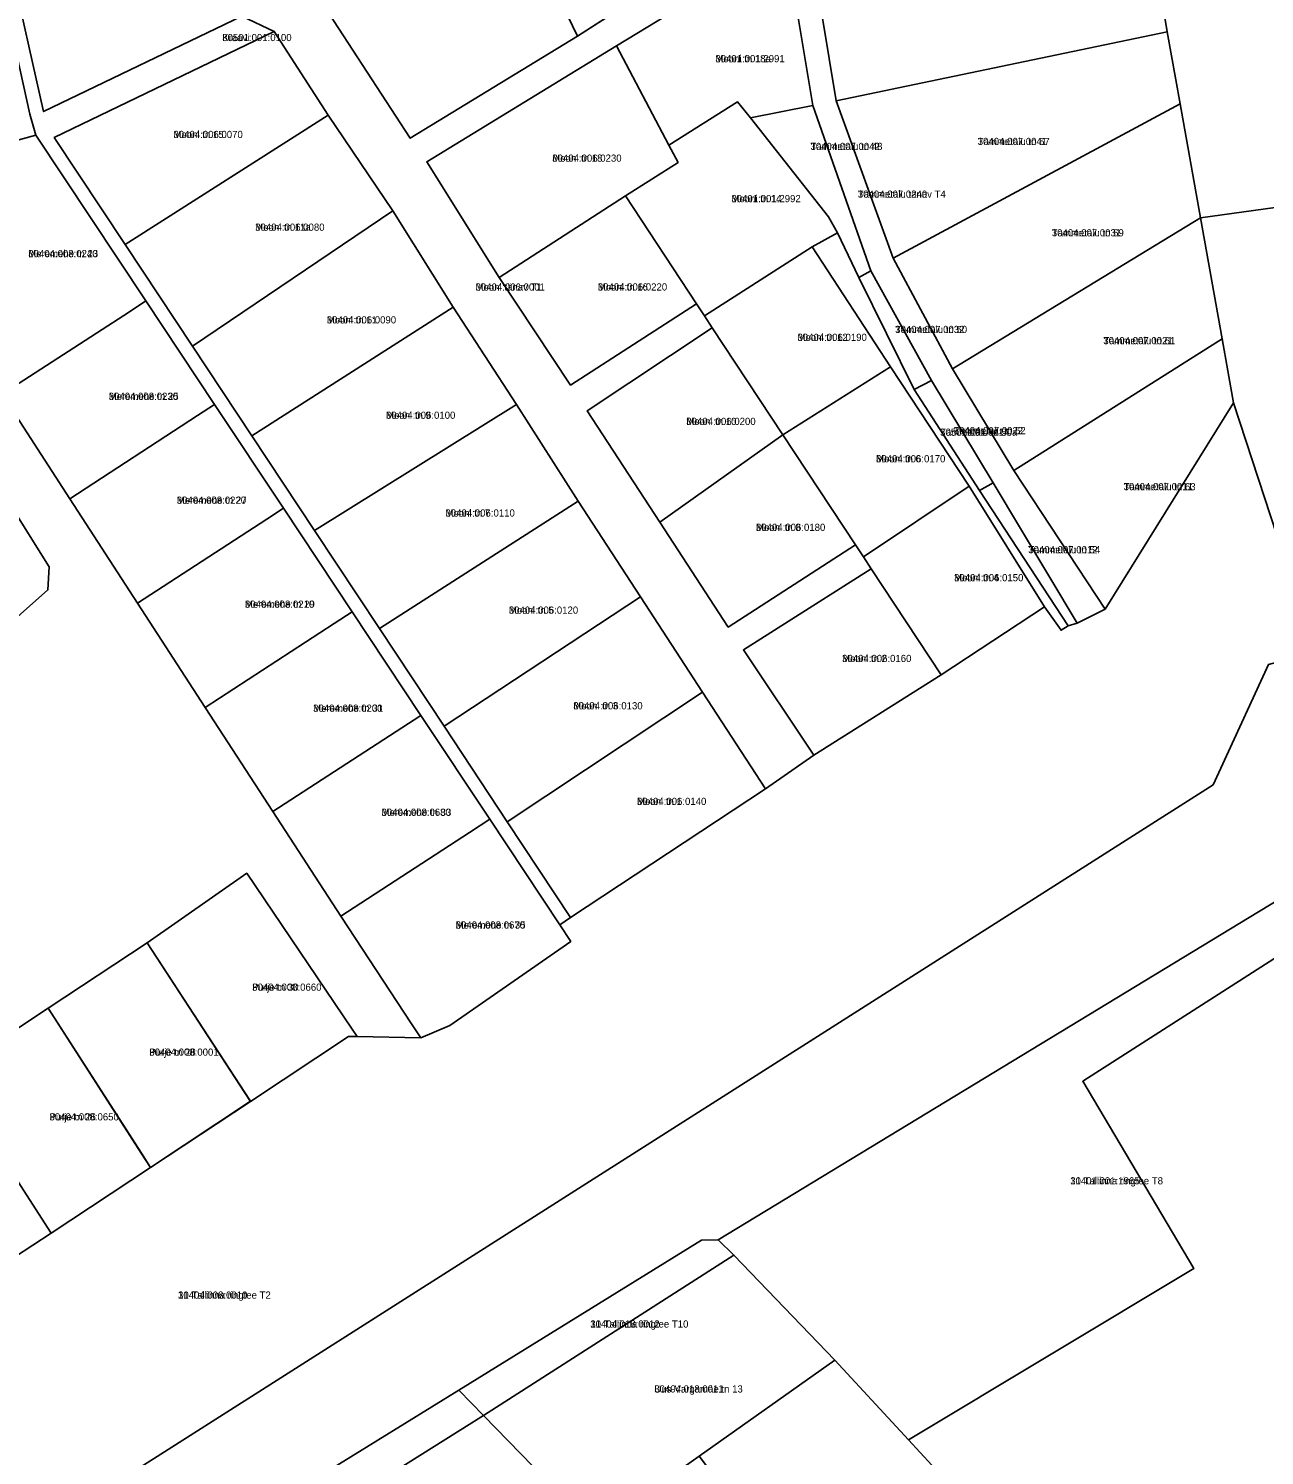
# Model space of a CAD drawing. Extents: x 542681 to 554572, y 6566489 to 6580482.
# Drawn here: x 544263.2 to 544521.7, y 6576713.2 to 6577011.6 of the extents above; entities that cross this region are included whole.
import ezdxf

# ---------------------------------------------------------------- set-up
doc = ezdxf.new("R2010")
doc.units = 0
for name, color, linetype in [('L_AADRESS', 7, 'Continuous'), ('PIIR', 7, 'Continuous'), ('TUNNUS', 7, 'Continuous')]:
    doc.layers.add(name, color=color, linetype=linetype)

msp = doc.modelspace()

# ---------------------------------------------------------------- linework, layer by layer
at = {"layer": 'PIIR'}
for points in [[(544047.37, 6576558.6), (544511.03, 6576853.43), (544522.56, 6576878.58), (544532.39, 6576881.26), (544735.78, 6577003.33), (545244.51, 6577326.53)], [(544232.86, 6577132.75), (544263.5, 6576993.69), (544264.77, 6576989.29), (544238.54, 6576982.1)], [(544259.33, 6577025.66), (544266.36, 6576994.23), (544307.82, 6577014.16), (544314.6, 6577010.96), (544268.59, 6576988.8), (544283.42, 6576966.41), (544297.5, 6576945.15), (544309.92, 6576926.39), (544323.02, 6576906.59), (544336.6, 6576886.08), (544350.13, 6576865.65), (544363.36, 6576845.67), (544376.61, 6576825.66), (544374.32, 6576824.14), (544359.67, 6576846.22), (544345.3, 6576867.89), (544330.91, 6576889.58), (544316.53, 6576911.27), (544302.13, 6576932.97), (544287.78, 6576954.61), (544264.77, 6576989.29), (544263.5, 6576993.69), (544232.86, 6577132.75)], [(544980.83, 6577118.49), (544817.23, 6577014.55), (544631.37, 6576896.55), (544550.43, 6576845.06), (544407.49, 6576758.27), (544403.98, 6576758.21), (544353.21, 6576726.8), (544302.38, 6576695.41)], [(544427.82, 6577022.67), (544432.12, 6576996.45), (544444.03, 6576963.57), (544456.44, 6576940.4), (544469.29, 6576919.14), (544488.38, 6576890.18), (544482.53, 6576887.2), (544465.01, 6576916.58), (544452.06, 6576937.98), (544439.36, 6576960.91), (544427.25, 6576995.48), (544422.87, 6577021.89)], [(544325.07, 6577016.28), (544343.06, 6576988.63), (544378.03, 6577009.97), (544392.94, 6577019.63)], [(544396.97, 6577014.51), (544386.23, 6577007.95), (544346.5, 6576983.72), (544361.68, 6576959.52), (544376.6, 6576937.03), (544402.93, 6576954), (544404.58, 6576951.49), (544406.24, 6576948.99), (544380.04, 6576931.62), (544395.27, 6576908.38), (544409.56, 6576886.41), (544436.19, 6576903.58), (544437.84, 6576901.08), (544439.49, 6576898.58), (544412.73, 6576881.63), (544427.47, 6576859.62), (544417.35, 6576852.57), (544404.2, 6576872.77), (544391.22, 6576892.72), (544378.18, 6576912.76), (544365.28, 6576932.97), (544352.02, 6576953.35), (544339.42, 6576973.43), (544325.88, 6576993.45), (544314.6, 6577010.96), (544307.82, 6577014.16)], [(544257.68, 6576935.15), (544271.85, 6576913.23), (544285.99, 6576891.43), (544300.14, 6576869.62), (544314.29, 6576847.82), (544328.56, 6576825.97), (544343.3, 6576803.42), (544345.26, 6576800.49), (544331.93, 6576800.8), (544330.92, 6576802.29), (544308.86, 6576834.92), (544288.05, 6576820.34), (544267.31, 6576806.67), (544248.12, 6576794.02)], [(544183.03, 6576703.47), (544209.73, 6576721.14), (544236.26, 6576738.69), (544241.04, 6576742.08), (544267.97, 6576759.66), (544288.75, 6576773.4), (544309.62, 6576787.21), (544330.16, 6576800.8), (544331.93, 6576800.8), (544345.26, 6576800.49), (544351.31, 6576803.07), (544376.64, 6576820.65), (544374.32, 6576824.14), (544376.61, 6576825.66), (544417.35, 6576852.57), (544427.47, 6576859.62), (544454.09, 6576876.45), (544475.75, 6576890.64), (544479.2, 6576885.76), (544480.66, 6576886.66), (544482.53, 6576887.2), (544488.38, 6576890.18), (544515.24, 6576933.3), (544528.21, 6576893.68)], [(544255.76, 6576884.03), (544267.28, 6576894.17), (544267.52, 6576899.03), (544248.56, 6576929.2)], [(544522.56, 6576878.58), (544511.03, 6576853.43), (544047.37, 6576558.6)], [(544461.91, 6576700.54), (544447.29, 6576716.4), (544506.96, 6576752.28), (544483.71, 6576791.42), (544554.71, 6576836.87), (544590.03, 6576770.52), (544597.56, 6576756.49), (544648.05, 6576660.25)]]:
    msp.add_lwpolyline(points, dxfattribs=at)
for points in [[(544508.33, 6576971.98), (544504.11, 6576995.85), (544501.39, 6577010.89), (544497.94, 6577031.69), (544494.23, 6577050.54), (544821.86, 6577171.21), (545190.34, 6577306.46), (545193.01, 6577298.86), (545134.4, 6577265.31), (545034.06, 6577204.02), (544998.25, 6577194.68), (544965.83, 6577161.37), (544819.08, 6577074.48), (544704.29, 6576998.99), (544688.78, 6576996.97)], [(544346.42, 6577070.5), (544372.29, 6577074.64), (544377.9, 6577042.29), (544392.89, 6577019.62), (544378.03, 6577009.97), (544365.54, 6577035.85), (544363.91, 6577040.25), (544348.97, 6577033.42), (544343.71, 6577060.87), (544341.95, 6577069.79)], [(544259.33, 6577025.66), (544303.68, 6577034.31), (544307.82, 6577014.16), (544266.36, 6576994.23)], [(544343.06, 6576988.63), (544325.07, 6577016.28), (544365.54, 6577035.85), (544378.03, 6577009.97)], [(544501.39, 6577010.89), (544432.12, 6576996.45), (544427.82, 6577022.67), (544497.94, 6577031.69)], [(544411.54, 6576996.24), (544397.14, 6576987.19), (544386.23, 6577007.95), (544396.97, 6577014.51), (544394.09, 6577018.12), (544422.87, 6577021.89), (544427.25, 6576995.48), (544414.19, 6576992.91)], [(544268.59, 6576988.8), (544314.6, 6577010.96), (544325.88, 6576993.45), (544283.42, 6576966.41)], [(544504.11, 6576995.85), (544444.03, 6576963.57), (544432.12, 6576996.45), (544501.39, 6577010.89)], [(544361.68, 6576959.52), (544346.5, 6576983.72), (544386.23, 6577007.95), (544397.14, 6576987.19), (544399.07, 6576983.59), (544388.08, 6576976.57)], [(544427.1, 6576965.92), (544404.58, 6576951.49), (544402.93, 6576954), (544388.08, 6576976.57), (544399.07, 6576983.59), (544397.14, 6576987.19), (544411.54, 6576996.24), (544414.19, 6576992.91), (544430.54, 6576972.24), (544432.39, 6576968.87)], [(544439.36, 6576960.91), (544436.91, 6576959.51), (544432.39, 6576968.87), (544430.54, 6576972.24), (544414.19, 6576992.91), (544427.25, 6576995.48)], [(544508.33, 6576971.98), (544456.44, 6576940.4), (544444.03, 6576963.57), (544504.11, 6576995.85)], [(544515.24, 6576933.3), (544512.86, 6576946.66), (544508.33, 6576971.98), (544688.78, 6576996.97), (544528.21, 6576893.68)], [(544283.42, 6576966.41), (544325.88, 6576993.45), (544339.42, 6576973.43), (544297.5, 6576945.15)], [(544252.75, 6576942.7), (544239.47, 6576979.52), (544238.54, 6576982.1), (544264.77, 6576989.29), (544287.78, 6576954.61), (544284.32, 6576952.37), (544257.68, 6576935.15)], [(544361.68, 6576959.52), (544388.08, 6576976.57), (544402.93, 6576954), (544376.6, 6576937.03)], [(544297.5, 6576945.15), (544339.42, 6576973.43), (544352.02, 6576953.35), (544309.92, 6576926.39)], [(544512.86, 6576946.66), (544469.29, 6576919.14), (544456.44, 6576940.4), (544508.33, 6576971.98)], [(544480.66, 6576886.66), (544479.2, 6576885.76), (544475.75, 6576890.64), (544459.97, 6576915.88), (544443.54, 6576940.83), (544427.1, 6576965.92), (544432.39, 6576968.87), (544436.91, 6576959.51), (544448.48, 6576936.07), (544462.12, 6576914.94)], [(544404.58, 6576951.49), (544427.1, 6576965.92), (544443.54, 6576940.83), (544420.99, 6576926.62), (544406.24, 6576948.99)], [(544452.06, 6576937.98), (544448.48, 6576936.07), (544436.91, 6576959.51), (544439.36, 6576960.91)], [(544257.68, 6576935.15), (544284.32, 6576952.37), (544287.78, 6576954.61), (544302.13, 6576932.97), (544298.54, 6576930.63), (544271.85, 6576913.23)], [(544309.92, 6576926.39), (544352.02, 6576953.35), (544365.28, 6576932.97), (544323.02, 6576906.59)], [(544380.04, 6576931.62), (544406.24, 6576948.99), (544420.99, 6576926.62), (544395.27, 6576908.38)], [(544515.24, 6576933.3), (544488.38, 6576890.18), (544469.29, 6576919.14), (544512.86, 6576946.66)], [(544420.99, 6576926.62), (544443.54, 6576940.83), (544459.97, 6576915.88), (544437.84, 6576901.08), (544436.19, 6576903.58)], [(544465.01, 6576916.58), (544462.12, 6576914.94), (544448.48, 6576936.07), (544452.06, 6576937.98)], [(544271.85, 6576913.23), (544298.54, 6576930.63), (544302.13, 6576932.97), (544316.53, 6576911.27), (544313.03, 6576909), (544285.99, 6576891.43)], [(544323.02, 6576906.59), (544365.28, 6576932.97), (544378.18, 6576912.76), (544336.6, 6576886.08)], [(544236.42, 6576892.73), (544234.62, 6576892.27), (544226.19, 6576923.47), (544248.56, 6576929.2), (544267.52, 6576899.03), (544267.28, 6576894.17), (544255.76, 6576884.03), (544251.02, 6576892.37), (544240.1, 6576887.96)], [(544395.27, 6576908.38), (544420.99, 6576926.62), (544436.19, 6576903.58), (544409.56, 6576886.41)], [(544437.84, 6576901.08), (544459.97, 6576915.88), (544475.75, 6576890.64), (544454.09, 6576876.45), (544439.49, 6576898.58)], [(544482.53, 6576887.2), (544480.66, 6576886.66), (544462.12, 6576914.94), (544465.01, 6576916.58)], [(544285.99, 6576891.43), (544313.03, 6576909), (544316.53, 6576911.27), (544330.91, 6576889.58), (544327.16, 6576887.15), (544300.14, 6576869.62)], [(544336.6, 6576886.08), (544378.18, 6576912.76), (544391.22, 6576892.72), (544350.13, 6576865.65)], [(544412.73, 6576881.63), (544439.49, 6576898.58), (544454.09, 6576876.45), (544427.47, 6576859.62)], [(544350.13, 6576865.65), (544391.22, 6576892.72), (544404.2, 6576872.77), (544363.36, 6576845.67)], [(544300.14, 6576869.62), (544327.16, 6576887.15), (544330.91, 6576889.58), (544345.3, 6576867.89), (544341.3, 6576865.31), (544314.29, 6576847.82)], [(544363.36, 6576845.67), (544404.2, 6576872.77), (544417.35, 6576852.57), (544376.61, 6576825.66)], [(544314.29, 6576847.82), (544341.3, 6576865.31), (544345.3, 6576867.89), (544359.67, 6576846.22), (544355.44, 6576843.47), (544328.56, 6576825.97)], [(544345.26, 6576800.49), (544343.3, 6576803.42), (544328.56, 6576825.97), (544355.44, 6576843.47), (544359.67, 6576846.22), (544374.32, 6576824.14), (544376.64, 6576820.65), (544351.31, 6576803.07)], [(544407.49, 6576758.27), (544550.43, 6576845.06), (544552.67, 6576840.76), (544554.71, 6576836.87), (544483.71, 6576791.42), (544506.96, 6576752.28), (544447.29, 6576716.4), (544431.89, 6576733.07), (544410.75, 6576755.06)], [(544308.44, 6576789.03), (544288.05, 6576820.34), (544308.86, 6576834.92), (544330.92, 6576802.29), (544331.93, 6576800.8), (544330.16, 6576800.8), (544309.62, 6576787.21)], [(544267.34, 6576806.7), (544288.05, 6576820.35), (544308.44, 6576789.04), (544309.62, 6576787.22), (544288.75, 6576773.41), (544286.84, 6576776.39)], [(544265.31, 6576763.78), (544251.34, 6576785.38), (544246.45, 6576792.92), (544248.12, 6576794.02), (544267.31, 6576806.67), (544286.81, 6576776.36), (544288.75, 6576773.4), (544267.97, 6576759.66)], [(544238.48, 6576746.17), (544224.33, 6576767.86), (544251.34, 6576785.38), (544265.31, 6576763.78), (544267.97, 6576759.66), (544241.04, 6576742.08)], [(544353.21, 6576726.8), (544403.98, 6576758.21), (544407.49, 6576758.27), (544410.75, 6576755.06), (544358.35, 6576721.52)], [(544410.75, 6576755.06), (544431.89, 6576733.07), (544403.51, 6576713.02), (544398.5, 6576709.48), (544381.68, 6576697.59), (544358.35, 6576721.52)], [(544461.91, 6576700.54), (544427.54, 6576681.22), (544403.51, 6576713.02), (544431.89, 6576733.07), (544447.29, 6576716.4)], [(544302.38, 6576695.41), (544353.21, 6576726.8), (544358.35, 6576721.52), (544307.53, 6576689.55)], [(544307.53, 6576689.55), (544358.35, 6576721.52), (544381.68, 6576697.59), (544362, 6576683.68), (544357.3, 6576680.36), (544331.46, 6576662.1)]]:
    msp.add_lwpolyline(points, close=True, dxfattribs=at)

# ---------------------------------------------------------------- texts
at = {"layer": 'L_AADRESS'}
for s, p in [('Kraavi', (544303.74, 6577008.96)), ('Mooni tn 18a', (544406.88, 6577004.54)), ('Mooni tn 15', (544293.53, 6576988.69)), ('Tammetalu tn 48', (544426.77, 6576986.19)), ('Tammetalu tn 57', (544461.76, 6576987.23)), ('Mooni tn 18', (544372.76, 6576983.74)), ('Tammetalu tänav T4', (544436.68, 6576976.21)), ('Mooni tn 14', (544410.23, 6576975.27)), ('Mooni tn 11a', (544310.63, 6576969.3)), ('Tammetalu tn 59', (544477.25, 6576968.12)), ('Meremehe tn 23', (544263.16, 6576963.77)), ('Mooni tänav T1', (544356.72, 6576956.78)), ('Mooni tn 16', (544382.29, 6576956.8)), ('Mooni tn 11', (544325.6, 6576949.91)), ('Mooni tn 12', (544424.06, 6576946.26)), ('Tammetalu tn 50', (544444.48, 6576947.91)), ('Tammetalu tn 61', (544488.02, 6576945.56)), ('Meremehe tn 25', (544279.99, 6576933.92)), ('Mooni tn 9', (544337.99, 6576929.97)), ('Mooni tn 10', (544400.8, 6576928.68)), ('Tammetalu tn 50a', (544453.88, 6576926.42)), ('Tammetalu tn 52', (544456.74, 6576926.75)), ('Mooni tn 6', (544440.48, 6576920.87)), ('Tammetalu tn 63', (544492.27, 6576915.03)), ('Meremehe tn 27', (544294.22, 6576912.2)), ('Mooni tn 7', (544350.43, 6576909.52)), ('Mooni tn 8', (544415.37, 6576906.52)), ('Tammetalu tn 54', (544472.32, 6576901.84)), ('Mooni tn 4', (544456.8, 6576895.99)), ('Meremehe tn 29', (544308.48, 6576890.45)), ('Mooni tn 5', (544363.68, 6576889.21)), ('Mooni tn 2', (544433.38, 6576879.1)), ('Meremehe tn 31', (544322.75, 6576868.7)), ('Mooni tn 3', (544377.16, 6576869.2)), ('Mooni tn 1', (544390.49, 6576849.21)), ('Meremehe tn 33', (544337.04, 6576846.93)), ('Meremehe tn 35', (544352.56, 6576823.35)), ('Purje tn 30', (544309.99, 6576810.35)), ('Purje tn 28', (544288.48, 6576796.76)), ('Purje tn 26', (544267.6, 6576783.23)), ('11 Tallinna ringtee T8', (544481.1, 6576769.85)), ('11 Tallinna ringtee T2', (544294.49, 6576745.95)), ('11 Tallinna ringtee T10', (544380.72, 6576739.9)), ('Uus-Vargamäe tn 13', (544394.1, 6576726.32))]:
    msp.add_text(s, height=1.5, dxfattribs=at).set_placement(p)
at = {"layer": 'TUNNUS'}
for s, p in [('30501:001:0100', (544303.74, 6577008.96)), ('30401:001:2991', (544406.88, 6577004.54)), ('30404:006:0070', (544293.53, 6576988.69)), ('30404:007:0042', (544426.77, 6576986.19)), ('30404:007:0041', (544461.76, 6576987.23)), ('30404:006:0230', (544372.76, 6576983.74)), ('30404:007:0240', (544436.68, 6576976.21)), ('30401:001:2992', (544410.23, 6576975.27)), ('30404:006:0080', (544310.63, 6576969.3)), ('30404:007:0031', (544477.25, 6576968.12)), ('30404:008:0240', (544263.16, 6576963.77)), ('30404:006:0001', (544356.72, 6576956.78)), ('30404:006:0220', (544382.29, 6576956.8)), ('30404:006:0090', (544325.6, 6576949.91)), ('30404:006:0190', (544424.06, 6576946.26)), ('30404:007:0032', (544444.48, 6576947.91)), ('30404:007:0021', (544488.02, 6576945.56)), ('30404:008:0230', (544279.99, 6576933.92)), ('30404:006:0100', (544337.99, 6576929.97)), ('30404:006:0200', (544400.8, 6576928.68)), ('30501:001:0114', (544453.88, 6576926.42)), ('30404:007:0022', (544456.74, 6576926.75)), ('30404:006:0170', (544440.48, 6576920.87)), ('30404:007:0011', (544492.27, 6576915.03)), ('30404:008:0220', (544294.22, 6576912.2)), ('30404:006:0110', (544350.43, 6576909.52)), ('30404:006:0180', (544415.37, 6576906.52)), ('30404:007:0012', (544472.32, 6576901.84)), ('30404:006:0150', (544456.8, 6576895.99)), ('30404:008:0210', (544308.48, 6576890.45)), ('30404:006:0120', (544363.68, 6576889.21)), ('30404:006:0160', (544433.38, 6576879.1)), ('30404:008:0200', (544322.75, 6576868.7)), ('30404:006:0130', (544377.16, 6576869.2)), ('30404:006:0140', (544390.49, 6576849.21)), ('30404:008:0680', (544337.04, 6576846.93)), ('30404:008:0670', (544352.56, 6576823.35)), ('30404:008:0660', (544309.99, 6576810.35)), ('30404:008:0001', (544288.48, 6576796.76)), ('30404:008:0650', (544267.6, 6576783.23)), ('30401:001:1965', (544481.1, 6576769.85)), ('30404:008:0010', (544294.49, 6576745.95)), ('30404:018:0012', (544380.72, 6576739.9)), ('30404:018:0011', (544394.1, 6576726.32))]:
    msp.add_text(s, height=1.5, dxfattribs=at).set_placement(p)

doc.saveas('drawing.dxf')
